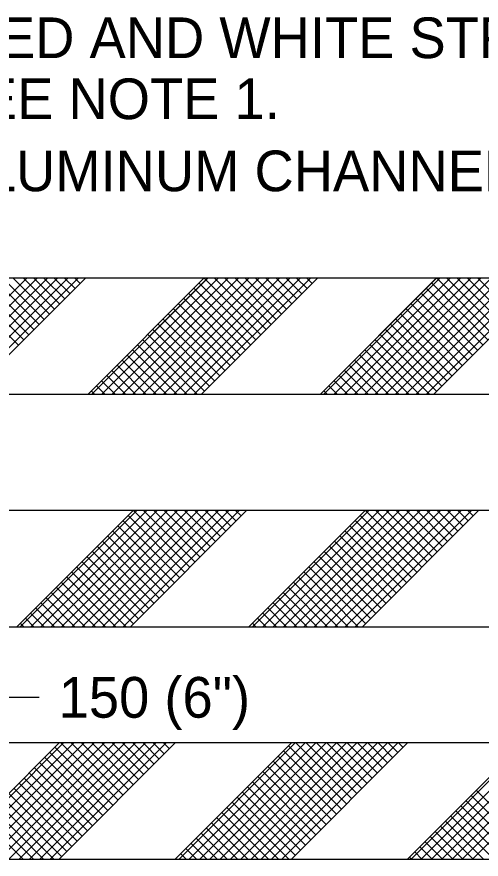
# Model space of a CAD drawing. Extents: x -4 to 901, y -468 to 720.
# Drawn here: x 218 to 256.4, y 608.8 to 678.4 of the extents above; entities that cross this region are included whole.
import ezdxf

# ---------------------------------------------------------------- set-up
doc = ezdxf.new("R2010")
doc.units = 0
doc.layers.add('2', color=7, linetype='Continuous')
doc.layers.add('3', color=7, linetype='Continuous')

msp = doc.modelspace()

# ---------------------------------------------------------------- linework, layer by layer
at = {"layer": '2'}
for p, q in [((214.1145, 647.195125), (223.7145, 656.795125)), ((223.94125, 647.205125), (233.54125, 656.805125)), ((223.94125, 647.205125), (233.54125, 656.805125)), ((233.3145, 647.195125), (242.9145, 656.795125)), ((243.14125, 647.205125), (252.74125, 656.805125)), ((243.14125, 647.205125), (252.73125, 656.795125)), ((252.5145, 647.195125), (262.1145, 656.795125)), ((218.05525, 628.005125), (227.64525, 637.595125)), ((227.4285, 627.995125), (237.0285, 637.595125)), ((237.25525, 628.005125), (246.85525, 637.605125)), ((246.6285, 627.995125), (256.2285, 637.595125)), ((211.9425, 608.795125), (221.5425, 618.395125)), ((211.9425, 608.795125), (221.5425, 618.395125)), ((211.9425, 608.795125), (221.5425, 618.395125)), ((221.5425, 608.795125), (231.1425, 618.395125)), ((231.1425, 608.795125), (240.7425, 618.395125)), ((231.1425, 608.795125), (240.7425, 618.395125)), ((231.1425, 608.795125), (240.7425, 618.395125)), ((231.1425, 608.795125), (240.7425, 618.395125)), ((240.7425, 608.795125), (250.3425, 618.395125)), ((250.3425, 608.795125), (259.9425, 618.395125))]:
    msp.add_line(p, q, dxfattribs=at)
for points in [[(140.2805, 656.795125), (140.2805, 647.195125), (284.2805, 647.195125), (284.2805, 656.795125)], [(140.2805, 637.595125), (140.2805, 627.995125), (271.9685, 627.995125), (271.9685, 637.595125)], [(140.2805, 618.395125), (140.2805, 608.795125), (271.9685, 608.795125), (271.9685, 618.395125)]]:
    msp.add_lwpolyline(points, close=True, dxfattribs=at)
for points in [[(209.26775, 647.195125), (218.86775, 656.795125)], [(210.11625, 647.195125), (219.71625, 656.795125)], [(210.96475, 647.195125), (220.56475, 656.795125)], [(211.81325, 647.195125), (221.41325, 656.795125)], [(212.66225, 647.195125), (222.26225, 656.795125)], [(213.51075, 647.195125), (223.11075, 656.795125)], [(219.03075, 652.109125), (214.33525, 656.801875)], [(219.455, 652.533625), (215.191, 656.795125)], [(219.879, 652.957875), (216.0395, 656.795125)], [(220.30325, 653.382375), (216.8885, 656.795125)], [(220.72725, 653.806625), (217.737, 656.795125)], [(221.1515, 654.230875), (218.58575, 656.795125)], [(221.57575, 654.655375), (219.43475, 656.795125)], [(221.99975, 655.079625), (220.28325, 656.795125)], [(222.424, 655.504125), (221.13225, 656.795125)], [(222.848, 655.928375), (221.98075, 656.795125)], [(223.27225, 656.352875), (222.82975, 656.795125)], [(224.23525, 647.205125), (233.83525, 656.805125)], [(224.23525, 647.205125), (233.82525, 656.795125)], [(225.07375, 647.195125), (234.67375, 656.795125)], [(225.92225, 647.195125), (235.52225, 656.795125)], [(226.77075, 647.195125), (236.37075, 656.795125)], [(227.61925, 647.195125), (237.21925, 656.795125)], [(228.46775, 647.195125), (238.06775, 656.795125)], [(229.31625, 647.195125), (238.91625, 656.795125)], [(230.16475, 647.195125), (239.76475, 656.795125)], [(231.01325, 647.195125), (240.61325, 656.795125)], [(231.86225, 647.195125), (241.46225, 656.795125)], [(232.71075, 647.195125), (242.31075, 656.795125)], [(238.2245, 652.106875), (233.53375, 656.797625)], [(238.6485, 652.530875), (234.38425, 656.795125)], [(239.073, 652.955375), (235.23325, 656.795125)], [(239.49725, 653.379625), (236.08175, 656.795125)], [(239.9215, 653.803875), (236.93025, 656.795125)], [(240.34575, 654.228125), (237.77875, 656.795125)], [(240.77, 654.652375), (238.62725, 656.795125)], [(241.19425, 655.076625), (239.47575, 656.795125)], [(241.6185, 655.500875), (240.32425, 656.795125)], [(242.04275, 655.925125), (241.17275, 656.795125)], [(242.467, 656.349375), (242.02125, 656.795125)], [(243.43525, 647.205125), (253.03525, 656.805125)], [(243.43525, 647.205125), (253.03525, 656.805125)], [(244.27375, 647.195125), (253.87375, 656.795125)], [(245.12225, 647.195125), (254.72225, 656.795125)], [(245.97075, 647.195125), (255.57075, 656.795125)], [(246.81925, 647.195125), (256.41925, 656.795125)], [(247.66775, 647.195125), (257.26775, 656.795125)], [(248.51625, 647.195125), (258.11625, 656.795125)], [(249.36475, 647.195125), (258.96475, 656.795125)], [(250.21325, 647.195125), (259.81325, 656.795125)], [(251.06225, 647.195125), (260.66225, 656.795125)], [(251.91075, 647.195125), (261.51075, 656.795125)], [(257.42025, 652.117125), (252.74575, 656.809625)], [(257.84525, 652.540625), (253.607, 656.795125)], [(258.27025, 652.964125), (254.454, 656.795125)], [(258.6955, 653.387625), (255.30125, 656.795125)], [(259.1205, 653.810875), (256.14775, 656.795125)], [(218.60675, 651.684875), (213.91125, 656.377625)], [(237.80025, 651.682625), (233.1095, 656.373375)], [(256.99525, 651.693625), (252.32075, 656.386125)], [(218.1825, 651.260375), (213.487, 655.953125)], [(236.9515, 650.833875), (232.26075, 655.524625)], [(237.376, 651.258375), (232.68525, 655.949125)], [(256.145, 650.846875), (251.4705, 655.539375)], [(256.57, 651.270125), (251.8955, 655.962625)], [(236.52725, 650.409625), (231.8365, 655.100375)], [(255.29475, 649.999875), (250.62025, 654.692375)], [(255.72, 650.423375), (251.0455, 655.115875)], [(235.67875, 649.561125), (230.988, 654.251875)], [(236.103, 649.985375), (231.41225, 654.676125)], [(254.86975, 649.576375), (250.19525, 654.268875)], [(234.83025, 648.712625), (230.1395, 653.403375)], [(235.2545, 649.136875), (230.56375, 653.827625)], [(254.0195, 648.729625), (249.345, 653.422125)], [(254.44475, 649.152875), (249.77025, 653.845375)], [(234.406, 648.288375), (229.71525, 652.979125)], [(253.5945, 648.306125), (248.92, 652.998625)], [(233.5575, 647.439875), (228.86675, 652.130625)], [(233.98175, 647.864125), (229.291, 652.554875)], [(252.7445, 647.459125), (248.07, 652.151625)], [(253.1695, 647.882625), (248.495, 652.575125)], [(232.10525, 647.195125), (228.01825, 651.282125)], [(232.95375, 647.195125), (228.4425, 651.706375)], [(251.31375, 647.195125), (247.21975, 651.304875)], [(252.16025, 647.195125), (247.64475, 651.728125)], [(231.25675, 647.195125), (227.594, 650.857875)], [(250.46675, 647.195125), (246.79475, 650.881375)], [(229.55975, 647.195125), (226.7455, 650.009375)], [(230.40825, 647.195125), (227.16975, 650.433625)], [(248.77275, 647.195125), (245.9445, 650.034375)], [(249.61975, 647.195125), (246.3695, 650.457875)], [(227.86275, 647.195125), (225.897, 649.160875)], [(228.71125, 647.195125), (226.32125, 649.585125)], [(247.079, 647.195125), (245.09425, 649.187625)], [(247.92625, 647.195125), (245.5195, 649.611125)], [(227.01425, 647.195125), (225.47275, 648.736625)], [(246.23225, 647.195125), (244.66925, 648.764125)], [(225.31675, 647.195125), (224.624, 647.887875)], [(226.16575, 647.195125), (225.0485, 648.312375)], [(244.53825, 647.195125), (243.819, 647.917125)], [(245.38525, 647.195125), (244.24425, 648.340625)], [(224.46825, 647.195125), (224.19975, 647.463625)], [(243.6915, 647.195125), (243.394, 647.493875)], [(218.34925, 628.005125), (227.94925, 637.605125)], [(219.18775, 627.995125), (228.78775, 637.595125)], [(220.03625, 627.995125), (229.63625, 637.595125)], [(220.88475, 627.995125), (230.48475, 637.595125)], [(221.73325, 627.995125), (231.33325, 637.595125)], [(222.58175, 627.995125), (232.18175, 637.595125)], [(223.43025, 627.995125), (233.03025, 637.595125)], [(224.27875, 627.995125), (233.87875, 637.595125)], [(225.12725, 627.995125), (234.72725, 637.595125)], [(225.97625, 627.995125), (235.57625, 637.595125)], [(226.82475, 627.995125), (236.42475, 637.595125)], [(232.33425, 632.917125), (227.65975, 637.609625)], [(232.75925, 633.340625), (228.52125, 637.595125)], [(233.18425, 633.764125), (229.368, 637.595125)], [(233.6095, 634.187625), (230.21525, 637.595125)], [(234.0345, 634.610875), (231.06175, 637.595125)], [(234.4595, 635.034375), (231.90875, 637.595125)], [(234.88475, 635.457875), (232.75575, 637.595125)], [(235.30975, 635.881375), (233.6025, 637.595125)], [(235.73475, 636.304625), (234.44925, 637.595125)], [(236.16, 636.728125), (235.29625, 637.595125)], [(236.585, 637.151625), (236.13325, 637.605125)], [(237.54925, 628.005125), (247.14925, 637.605125)], [(238.38775, 627.995125), (247.98775, 637.595125)], [(239.23625, 627.995125), (248.83625, 637.595125)], [(240.08475, 627.995125), (249.68475, 637.595125)], [(240.93325, 627.995125), (250.53325, 637.595125)], [(241.78175, 627.995125), (251.38175, 637.595125)], [(242.63025, 627.995125), (252.23025, 637.595125)], [(243.47875, 627.995125), (253.07875, 637.595125)], [(244.32725, 627.995125), (253.92725, 637.595125)], [(245.17625, 627.995125), (254.77625, 637.595125)], [(246.02475, 627.995125), (255.62475, 637.595125)], [(251.53425, 632.917125), (246.8745, 637.595125)], [(251.95925, 633.340625), (247.72125, 637.595125)], [(252.38425, 633.764125), (248.568, 637.595125)], [(252.8095, 634.187625), (249.41525, 637.595125)], [(253.2345, 634.610875), (250.26175, 637.595125)], [(253.6595, 635.034375), (251.10875, 637.595125)], [(254.08475, 635.457875), (251.95575, 637.595125)], [(254.50975, 635.881375), (252.8025, 637.595125)], [(254.93475, 636.304625), (253.64925, 637.595125)], [(255.36, 636.728125), (254.49625, 637.595125)], [(255.785, 637.151625), (255.33325, 637.605125)], [(231.484, 632.070125), (226.8095, 636.762625)], [(231.90925, 632.493625), (227.23475, 637.186125)], [(250.684, 632.070375), (246.01125, 636.761125)], [(251.109, 632.493625), (246.4355, 637.185375)], [(230.634, 631.223375), (225.9595, 635.915875)], [(231.059, 631.646875), (226.3845, 636.339375)], [(249.83375, 631.223375), (245.16275, 635.912625)], [(250.259, 631.646875), (245.587, 636.336875)], [(230.20875, 630.799875), (225.53425, 635.492375)], [(249.40875, 630.799875), (244.7385, 635.488375)], [(229.35875, 629.952875), (224.68425, 634.645375)], [(229.78375, 630.376375), (225.10925, 635.068875)], [(248.5585, 629.953125), (243.89, 634.639875)], [(248.98375, 630.376625), (244.31425, 635.064125)], [(228.9335, 629.529625), (224.259, 634.222125)], [(248.1335, 629.529625), (243.46575, 634.215625)], [(228.0835, 628.682625), (223.409, 633.375125)], [(228.5085, 629.106125), (223.834, 633.798625)], [(247.28325, 628.682875), (242.61725, 633.367125)], [(247.70825, 629.106125), (243.04125, 633.791125)], [(227.07425, 627.995125), (222.55875, 632.528125)], [(227.6585, 628.259125), (222.984, 632.951625)], [(246.27425, 627.995125), (241.7685, 632.518375)], [(246.85825, 628.259375), (242.193, 632.942875)], [(226.22775, 627.995125), (222.13375, 632.104875)], [(245.4275, 627.995125), (241.34425, 632.094125)], [(224.53375, 627.995125), (221.2835, 631.257875)], [(225.38075, 627.995125), (221.70875, 631.681375)], [(243.73375, 627.995125), (240.49575, 631.245625)], [(244.581, 627.995125), (240.92025, 631.670125)], [(222.84025, 627.995125), (220.4335, 630.411125)], [(223.68675, 627.995125), (220.8715, 630.821375)], [(242.04, 627.995125), (239.64725, 630.397125)], [(242.887, 627.995125), (240.0715, 630.821375)], [(221.993, 627.995125), (220.00825, 629.987625)], [(241.19325, 627.995125), (239.223, 629.972875)], [(220.29925, 627.995125), (219.1745, 629.124375)], [(221.14625, 627.995125), (219.58325, 629.564125)], [(239.4995, 627.995125), (238.3745, 629.124375)], [(240.34625, 627.995125), (238.79875, 629.548625)], [(218.6055, 627.995125), (218.326, 628.275875)], [(219.45225, 627.995125), (218.75, 628.699875)], [(237.80575, 627.995125), (237.526, 628.275875)], [(238.6525, 627.995125), (237.95025, 628.700125)], [(219.8905, 622.141125), (215.0905, 622.141125), (210.6785, 612.477125)], [(212.29725, 608.795125), (221.89925, 618.395125)], [(213.14575, 608.795125), (222.74775, 618.395125)], [(213.9945, 608.795125), (223.5965, 618.395125)], [(214.84325, 608.795125), (224.44525, 618.395125)], [(215.69175, 608.795125), (225.294, 618.395125)], [(216.54025, 608.795125), (226.14225, 618.395125)], [(217.38875, 608.795125), (226.99075, 618.395125)], [(218.2375, 608.795125), (227.83975, 618.395125)], [(219.08625, 608.795125), (228.68825, 618.395125)], [(219.93475, 608.795125), (229.53675, 618.395125)], [(220.7835, 608.795125), (230.38525, 618.395125)], [(225.98975, 613.242375), (221.18975, 618.042375)], [(226.414, 613.666625), (221.6855, 618.395125)], [(226.83825, 614.090875), (222.534, 618.395125)], [(227.26275, 614.515375), (223.383, 618.395125)], [(227.687, 614.939625), (224.2315, 618.395125)], [(228.11125, 615.363875), (225.08, 618.395125)], [(228.5355, 615.788125), (225.9285, 618.395125)], [(228.95975, 616.212375), (226.777, 618.395125)], [(229.384, 616.636625), (227.6255, 618.395125)], [(229.80825, 617.060875), (228.474, 618.395125)], [(230.2325, 617.485125), (229.3225, 618.395125)], [(230.65675, 617.909375), (230.171, 618.395125)], [(231.46425, 608.795125), (241.06625, 618.395125)], [(232.2845, 608.795125), (241.8845, 618.393125)], [(233.1615, 608.795125), (242.7635, 618.395125)], [(234.01025, 608.795125), (243.61225, 618.395125)], [(234.85875, 608.795125), (244.46075, 618.395125)], [(235.70725, 608.795125), (245.30925, 618.395125)], [(236.55575, 608.795125), (246.15775, 618.395125)], [(237.4045, 608.795125), (247.0065, 618.395125)], [(238.25325, 608.795125), (247.85525, 618.395125)], [(239.10175, 608.795125), (248.70375, 618.395125)], [(239.9505, 608.795125), (249.5525, 618.395125)], [(245.30825, 613.357625), (240.505, 618.157625)], [(245.73225, 613.782125), (241.116, 618.395125)], [(246.1565, 614.206375), (241.965, 618.395125)], [(246.5805, 614.630875), (242.81375, 618.395125)], [(247.00475, 615.055375), (243.66275, 618.395125)], [(247.42875, 615.479625), (244.51125, 618.395125)], [(247.853, 615.904125), (245.36025, 618.395125)], [(248.277, 616.328375), (246.20875, 618.395125)], [(248.70125, 616.752875), (247.058, 618.395125)], [(249.12525, 617.177375), (247.90675, 618.395125)], [(249.5495, 617.601625), (248.7555, 618.395125)], [(249.9735, 618.026125), (249.60425, 618.395125)], [(250.635, 608.795125), (260.237, 618.395125)], [(251.4835, 608.795125), (261.0855, 618.395125)], [(252.33225, 608.795125), (261.93425, 618.395125)], [(253.181, 608.795125), (262.783, 618.395125)], [(254.0295, 608.795125), (263.6315, 618.395125)], [(254.878, 608.795125), (264.48, 618.395125)], [(255.7265, 608.795125), (265.3285, 618.395125)], [(225.14125, 612.393875), (220.34125, 617.193875)], [(225.5655, 612.818125), (220.7655, 617.618125)], [(244.46, 612.508875), (239.6565, 617.309125)], [(244.884, 612.933125), (240.0805, 617.733125)], [(224.717, 611.969625), (219.917, 616.769625)], [(243.61175, 611.660125), (238.80825, 616.460375)], [(244.036, 612.084375), (239.2325, 616.884625)], [(223.8685, 611.121125), (219.0685, 615.921125)], [(224.29275, 611.545375), (219.49275, 616.345375)], [(243.18775, 611.235625), (238.38425, 616.035875)], [(223.02, 610.272625), (218.22, 615.072625)], [(223.44425, 610.696875), (218.64425, 615.496875)], [(242.3395, 610.386875), (237.536, 615.187125)], [(242.7635, 610.811125), (237.96, 615.611375)], [(222.59575, 609.848375), (217.79575, 614.648375)], [(241.91525, 609.962375), (237.11175, 614.762625)], [(260.83025, 609.682875), (256.03025, 614.482875)], [(221.747, 608.999625), (216.947, 613.799625)], [(222.17125, 609.423875), (217.37125, 614.223875)], [(241.067, 609.113625), (236.2635, 613.913875)], [(241.49125, 609.538125), (236.68775, 614.338375)], [(260.406, 609.258625), (255.606, 614.058625)], [(220.2545, 608.795125), (216.0985, 612.951125)], [(221.103, 608.795125), (216.52275, 613.375375)], [(239.68825, 608.795125), (235.41525, 613.065125)], [(240.537, 608.795125), (235.8395, 613.489375)], [(259.1725, 608.795125), (254.7575, 613.210125)], [(259.98175, 608.834375), (255.18175, 613.634375)], [(219.406, 608.795125), (215.67425, 612.526875)], [(238.83925, 608.795125), (234.99125, 612.640625)], [(257.4755, 608.795125), (253.909, 612.361625)], [(258.324, 608.795125), (254.33325, 612.785875)], [(218.5575, 608.795125), (215.25, 612.102625)], [(237.14175, 608.795125), (234.143, 611.791875)], [(237.99025, 608.795125), (234.567, 612.216125)], [(256.627, 608.795125), (253.48475, 611.937375)], [(235.44425, 608.795125), (233.29475, 610.943125)], [(236.29275, 608.795125), (233.71875, 611.367375)], [(254.93, 608.795125), (252.63625, 611.088875)], [(255.7785, 608.795125), (253.0605, 611.513125)], [(234.59525, 608.795125), (232.8705, 610.518625)], [(253.233, 608.795125), (251.78775, 610.240375)], [(254.0815, 608.795125), (252.212, 610.664625)], [(232.8975, 608.795125), (232.02225, 609.669875)], [(233.7465, 608.795125), (232.4465, 610.094125)], [(252.3845, 608.795125), (251.3635, 609.816125)], [(232.04875, 608.795125), (231.59825, 609.245375)], [(250.6875, 608.795125), (250.515, 608.967625)], [(251.536, 608.795125), (250.93925, 609.391875)]]:
    msp.add_lwpolyline(points, dxfattribs=at)

# ---------------------------------------------------------------- texts
at = {"layer": '3'}
for s, height, p in [('ALTERNATE RED AND WHITE STRIPES, TRAFFIC', 3.359988, (185.6025, 674.959125)), ('SIDE ONLY, SEE NOTE 1.', 3.359988, (185.6025, 669.919125)), ('EXTRUDED ALUMINUM CHANNEL,', 3.359988, (186.5185, 663.965125)), ('150 (6")', 3.36, (221.495, 620.479125))]:
    msp.add_text(s, height=height, dxfattribs=at).set_placement(p)

doc.saveas('drawing.dxf')
